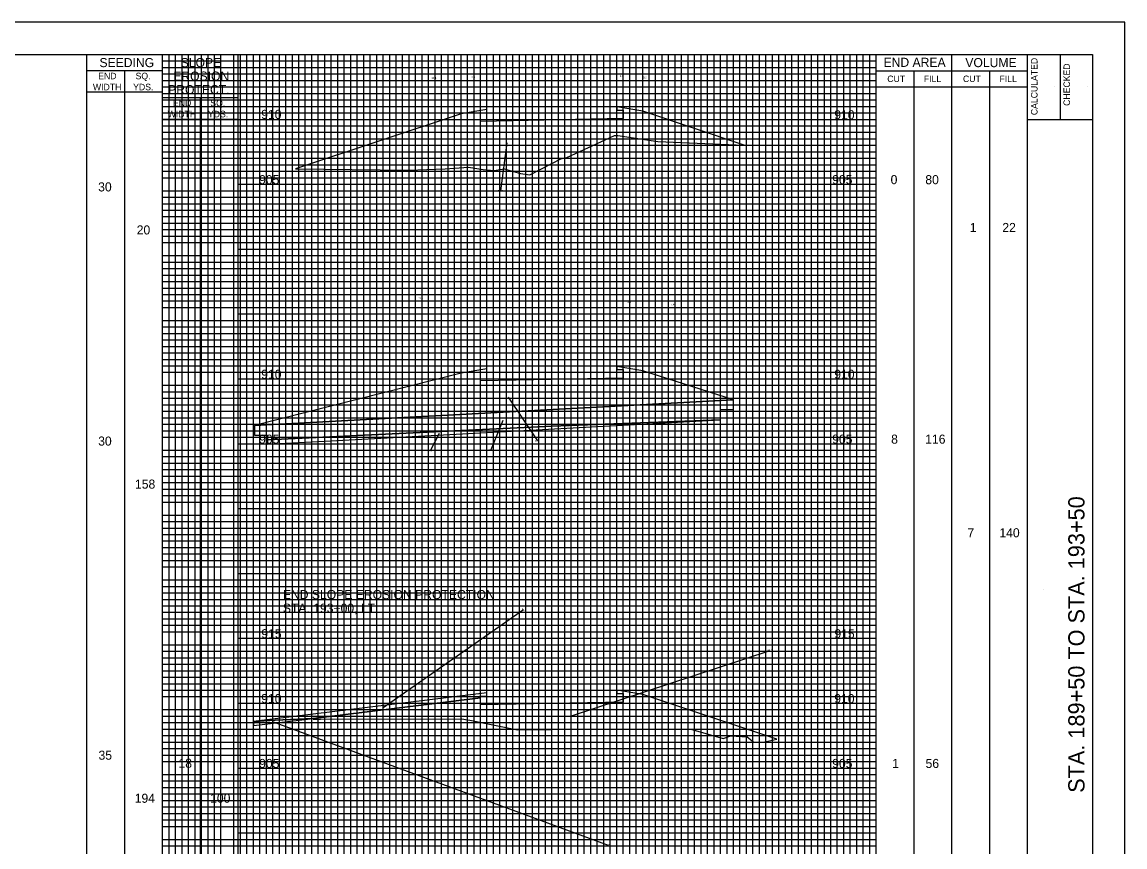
# Model space of a CAD drawing. Extents: x -73 to 160, y -2 to 1877.
# Drawn here: x 75 to 160, y 1078.9 to 1142.5 of the extents above; entities that cross this region are included whole.
import ezdxf

# ---------------------------------------------------------------- set-up
doc = ezdxf.new("R2010")
doc.units = 0
for name, color, linetype in [('DR_P_Flood_Boundary', 7, 'Continuous'), ('GK_Cells', 7, 'Continuous'), ('RD_X_Fence', 7, 'Continuous'), ('TX_X_5', 7, 'Continuous'), ('UT_P_Water_Cells', 7, 'Continuous'), ('XS_P_Pavt_Surface', 7, 'Continuous'), ('XS_X_Ground_Line', 7, 'Continuous')]:
    doc.layers.add(name, color=color, linetype=linetype)

msp = doc.modelspace()

# ---------------------------------------------------------------- linework, layer by layer
at = {"layer": 'DR_P_Flood_Boundary'}
for p, q in [((95.832, 1035), (95.832, 1140)), ((100.832, 1035), (100.832, 1140)), ((105.832, 1035), (105.832, 1140)), ((110.832, 1035), (110.832, 1140)), ((115.832, 1035), (115.832, 1140)), ((120.832, 1035), (120.832, 1140)), ((125.832, 1035), (125.832, 1140)), ((130.832, 1035), (130.832, 1140)), ((135.832, 1035), (135.832, 1140)), ((85.832, 1135), (140.832, 1135)), ((91.665, 1130), (140.832, 1130)), ((91.665, 1125), (140.832, 1125)), ((91.665, 1120), (140.832, 1120)), ((91.665, 1115), (140.832, 1115)), ((91.665, 1110), (140.832, 1110)), ((91.665, 1105), (140.832, 1105)), ((91.665, 1100), (140.832, 1100)), ((91.665, 1095), (140.832, 1095)), ((91.665, 1090), (140.832, 1090)), ((91.665, 1085), (140.832, 1085)), ((91.665, 1080), (140.832, 1080))]:
    msp.add_line(p, q, dxfattribs=at)
at = {"layer": 'GK_Cells'}
for p, q in [((152.5, 1035), (152.5, 1140)), ((155, 1140), (155, 1135)), ((152.5, 1135), (157.5, 1135))]:
    msp.add_line(p, q, dxfattribs=at)
msp.add_lwpolyline([(0, 1140), (157.5, 1140), (157.5, 1035), (0, 1035)], close=True, dxfattribs=at)
at = {"layer": 'RD_X_Fence'}
for p, q in [((110.832, 1135.76), (108.832, 1135.427)), ((122.832, 1135.627), (120.832, 1135.96)), ((120.832, 1135.71), (121.332, 1135.72)), ((121.332, 1135.72), (121.332, 1135.053)), ((130.666, 1133.016), (122.832, 1135.627)), ((108.832, 1135.427), (96.073, 1131.173)), ((110.332, 1135.5), (110.832, 1135.51)), ((110.332, 1134.833), (110.332, 1135.5)), ((121.332, 1135.053), (110.332, 1134.833)), ((112.363, 1133.182), (111.883, 1129.484)), ((108.832, 1115.427), (92.913, 1111.4)), ((110.832, 1115.76), (108.832, 1115.427)), ((110.332, 1115.5), (110.832, 1115.51)), ((110.332, 1114.833), (110.332, 1115.5)), ((122.832, 1115.627), (120.832, 1115.96)), ((120.832, 1115.71), (121.332, 1115.72)), ((121.332, 1115.72), (121.332, 1115.053)), ((129.832, 1113.38), (122.832, 1115.627)), ((121.332, 1115.053), (110.332, 1114.833)), ((112.458, 1113.586), (114.719, 1110.214)), ((129.832, 1113.38), (92.913, 1111.4)), ((92.913, 1111.4), (129.832, 1113.38)), ((129.832, 1112.63), (129.832, 1113.38)), ((115.832, 1111.343), (128.832, 1111.842)), ((128.832, 1112.63), (129.832, 1112.63)), ((128.832, 1111.842), (128.832, 1112.63)), ((128.832, 1111.826), (128.832, 1111.842)), ((92.913, 1111.4), (92.913, 1110.65)), ((93.913, 1110.307), (115.832, 1111.343)), ((112.056, 1111.792), (111.124, 1109.523)), ((92.913, 1110.65), (93.913, 1110.65)), ((93.913, 1110.65), (93.913, 1110.307)), ((93.913, 1110.307), (93.913, 1109.954)), ((107.153, 1110.794), (106.465, 1109.448)), ((102.834, 1089.661), (113.657, 1097.229)), ((117.267, 1088.992), (132.665, 1094.068)), ((110.832, 1090.792), (92.832, 1088.597)), ((122.832, 1090.659), (120.832, 1090.992)), ((120.832, 1090.742), (121.332, 1090.752)), ((121.332, 1090.752), (121.332, 1090.086)), ((133.172, 1087.213), (122.832, 1090.659)), ((110.332, 1090.401), (97.435, 1088.828)), ((97.435, 1088.828), (110.332, 1090.401)), ((110.332, 1090.532), (110.832, 1090.542)), ((110.332, 1090.401), (110.332, 1090.532)), ((110.332, 1089.866), (110.332, 1090.401)), ((121.332, 1090.086), (110.332, 1089.866)), ((92.832, 1088.267), (97.435, 1088.828)), ((94.508, 1088.677), (92.832, 1088.597)), ((92.832, 1088.597), (92.832, 1088.267)), ((94.359, 1088.562), (120.181, 1079.042)), ((97.435, 1088.828), (94.508, 1088.677))]:
    msp.add_line(p, q, dxfattribs=at)
for points in [[(110.832, 1135.51), (110.832, 1135.656), (110.832, 1135.76)], [(120.832, 1135.96), (120.832, 1135.856), (120.832, 1135.71)], [(96.073, 1131.173), (104.784, 1131.084), (107.603, 1131.193), (109.398, 1131.309), (110.538, 1131.143), (111.396, 1131.055), (112.145, 1131.194), (113.421, 1130.814), (114.132, 1130.712), (115.833, 1131.587), (116.533, 1131.948), (116.999, 1132.07), (120.651, 1133.759), (120.929, 1133.75), (123.991, 1133.297), (130.666, 1133.016)], [(110.832, 1115.51), (110.832, 1115.656), (110.832, 1115.76)], [(120.832, 1115.96), (120.832, 1115.856), (120.832, 1115.71)], [(128.832, 1111.842), (115.832, 1111.343), (93.913, 1110.307)], [(93.913, 1109.954), (108.948, 1110.76), (128.832, 1111.826)], [(110.832, 1090.542), (110.832, 1090.688), (110.832, 1090.792)], [(120.832, 1090.992), (120.832, 1090.888), (120.832, 1090.742)], [(92.832, 1088.597), (94.508, 1088.677), (97.435, 1088.828)], [(97.435, 1088.828), (97.444, 1088.756)], [(97.444, 1088.756), (97.991, 1088.773), (108.881, 1088.802), (109.332, 1088.712)], [(109.332, 1088.712), (109.332, 1088.712)], [(109.332, 1088.712), (109.512, 1088.676), (113.184, 1087.945), (115.832, 1087.956)], [(115.832, 1087.956), (122.332, 1087.984), (126.55, 1088.003), (129.023, 1087.274), (129.616, 1087.479), (130.873, 1087.395), (131.395, 1086.992), (132.249, 1087.017), (133.172, 1087.213)]]:
    msp.add_lwpolyline(points, dxfattribs=at)
at = {"layer": 'TX_X_5'}
msp.add_lwpolyline([(-10, 1032.5), (160, 1032.5), (160, 1142.5), (-10, 1142.5)], close=True, dxfattribs=at)
at = {"layer": 'UT_P_Water_Cells'}
for p, q in [((86.332, 1035), (86.332, 1140)), ((86.832, 1035), (86.832, 1140)), ((87.332, 1035), (87.332, 1140)), ((87.832, 1035), (87.832, 1140)), ((88.332, 1035), (88.332, 1140)), ((88.832, 1035), (88.832, 1140)), ((89.332, 1035), (89.332, 1140)), ((89.832, 1035), (89.832, 1140)), ((90.332, 1035), (90.332, 1140)), ((91.332, 1035), (91.332, 1140)), ((91.832, 1035), (91.832, 1140)), ((92.332, 1035), (92.332, 1140)), ((92.832, 1035), (92.832, 1140)), ((93.332, 1035), (93.332, 1140)), ((93.832, 1035), (93.832, 1140)), ((94.332, 1035), (94.332, 1140)), ((94.832, 1035), (94.832, 1140)), ((95.332, 1035), (95.332, 1140)), ((96.332, 1035), (96.332, 1140)), ((96.832, 1035), (96.832, 1140)), ((97.332, 1035), (97.332, 1140)), ((97.832, 1035), (97.832, 1140)), ((98.332, 1035), (98.332, 1140)), ((98.832, 1035), (98.832, 1140)), ((99.332, 1035), (99.332, 1140)), ((99.832, 1035), (99.832, 1140)), ((100.332, 1035), (100.332, 1140)), ((101.332, 1035), (101.332, 1140)), ((101.832, 1035), (101.832, 1140)), ((102.332, 1035), (102.332, 1140)), ((102.832, 1035), (102.832, 1140)), ((103.332, 1035), (103.332, 1140)), ((103.832, 1035), (103.832, 1140)), ((104.332, 1035), (104.332, 1140)), ((104.832, 1035), (104.832, 1140)), ((105.332, 1035), (105.332, 1140)), ((106.332, 1035), (106.332, 1140)), ((106.832, 1035), (106.832, 1140)), ((107.332, 1035), (107.332, 1140)), ((107.832, 1035), (107.832, 1140)), ((108.332, 1035), (108.332, 1140)), ((108.832, 1035), (108.832, 1140)), ((109.332, 1035), (109.332, 1140)), ((109.832, 1035), (109.832, 1140)), ((110.332, 1035), (110.332, 1140)), ((111.332, 1035), (111.332, 1140)), ((111.832, 1035), (111.832, 1140)), ((112.332, 1035), (112.332, 1140)), ((112.832, 1035), (112.832, 1140)), ((113.332, 1035), (113.332, 1140)), ((113.832, 1035), (113.832, 1140)), ((114.332, 1035), (114.332, 1140)), ((114.832, 1035), (114.832, 1140)), ((115.332, 1035), (115.332, 1140)), ((116.332, 1035), (116.332, 1140)), ((116.832, 1035), (116.832, 1140)), ((117.332, 1035), (117.332, 1140)), ((117.832, 1035), (117.832, 1140)), ((118.332, 1035), (118.332, 1140)), ((118.832, 1035), (118.832, 1140)), ((119.332, 1035), (119.332, 1140)), ((119.832, 1035), (119.832, 1140)), ((120.332, 1035), (120.332, 1140)), ((121.332, 1035), (121.332, 1140)), ((121.832, 1035), (121.832, 1140)), ((122.332, 1035), (122.332, 1140)), ((122.832, 1035), (122.832, 1140)), ((123.332, 1035), (123.332, 1140)), ((123.832, 1035), (123.832, 1140)), ((124.332, 1035), (124.332, 1140)), ((124.832, 1035), (124.832, 1140)), ((125.332, 1035), (125.332, 1140)), ((126.332, 1035), (126.332, 1140)), ((126.832, 1035), (126.832, 1140)), ((127.332, 1035), (127.332, 1140)), ((127.832, 1035), (127.832, 1140)), ((128.332, 1035), (128.332, 1140)), ((128.832, 1035), (128.832, 1140)), ((129.332, 1035), (129.332, 1140)), ((129.832, 1035), (129.832, 1140)), ((130.332, 1035), (130.332, 1140)), ((131.332, 1035), (131.332, 1140)), ((131.832, 1035), (131.832, 1140)), ((132.332, 1035), (132.332, 1140)), ((132.832, 1035), (132.832, 1140)), ((133.332, 1035), (133.332, 1140)), ((133.832, 1035), (133.832, 1140)), ((134.332, 1035), (134.332, 1140)), ((134.832, 1035), (134.832, 1140)), ((135.332, 1035), (135.332, 1140)), ((136.332, 1035), (136.332, 1140)), ((136.832, 1035), (136.832, 1140)), ((137.332, 1035), (137.332, 1140)), ((137.832, 1035), (137.832, 1140)), ((138.332, 1035), (138.332, 1140)), ((138.832, 1035), (138.832, 1140)), ((139.332, 1035), (139.332, 1140)), ((139.832, 1035), (139.832, 1140)), ((140.332, 1035), (140.332, 1140)), ((85.832, 1139.5), (140.832, 1139.5)), ((85.832, 1139), (140.832, 1139)), ((85.832, 1138.5), (140.832, 1138.5)), ((85.832, 1138), (140.832, 1138)), ((85.832, 1137.5), (140.832, 1137.5)), ((85.832, 1137), (140.832, 1137)), ((85.832, 1136.5), (140.832, 1136.5)), ((85.832, 1136), (140.832, 1136)), ((85.832, 1135.5), (140.832, 1135.5)), ((85.832, 1134.5), (140.832, 1134.5)), ((85.832, 1134), (140.832, 1134)), ((85.832, 1133.5), (140.832, 1133.5)), ((85.832, 1133), (140.832, 1133)), ((85.832, 1132.5), (140.832, 1132.5)), ((85.832, 1132), (140.832, 1132)), ((85.832, 1131.5), (140.832, 1131.5)), ((85.832, 1131), (140.832, 1131)), ((85.832, 1130.5), (140.832, 1130.5)), ((85.832, 1129.5), (140.832, 1129.5)), ((85.832, 1129), (140.832, 1129)), ((85.832, 1128.5), (140.832, 1128.5)), ((85.832, 1128), (140.832, 1128)), ((85.832, 1127.5), (140.832, 1127.5)), ((85.832, 1127), (140.832, 1127)), ((85.832, 1126.5), (140.832, 1126.5)), ((85.832, 1126), (140.832, 1126)), ((85.832, 1125.5), (140.832, 1125.5)), ((85.832, 1124.5), (140.832, 1124.5)), ((85.832, 1124), (140.832, 1124)), ((85.832, 1123.5), (140.832, 1123.5)), ((85.832, 1123), (140.832, 1123)), ((85.832, 1122.5), (140.832, 1122.5)), ((85.832, 1122), (140.832, 1122)), ((85.832, 1121.5), (140.832, 1121.5)), ((85.832, 1121), (140.832, 1121)), ((85.832, 1120.5), (140.832, 1120.5)), ((85.832, 1119.5), (140.832, 1119.5)), ((85.832, 1119), (140.832, 1119)), ((85.832, 1118.5), (140.832, 1118.5)), ((85.832, 1118), (140.832, 1118)), ((85.832, 1117.5), (140.832, 1117.5)), ((85.832, 1117), (140.832, 1117)), ((85.832, 1116.5), (140.832, 1116.5)), ((85.832, 1116), (140.832, 1116)), ((85.832, 1115.5), (140.832, 1115.5)), ((85.832, 1114.5), (140.832, 1114.5)), ((85.832, 1114), (140.832, 1114)), ((85.832, 1113.5), (140.832, 1113.5)), ((85.832, 1113), (140.832, 1113)), ((85.832, 1112.5), (140.832, 1112.5)), ((85.832, 1112), (140.832, 1112)), ((85.832, 1111.5), (140.832, 1111.5)), ((85.832, 1111), (140.832, 1111)), ((85.832, 1110.5), (140.832, 1110.5)), ((85.832, 1109.5), (140.832, 1109.5)), ((85.832, 1109), (140.832, 1109)), ((85.832, 1108.5), (140.832, 1108.5)), ((85.832, 1108), (140.832, 1108)), ((85.832, 1107.5), (140.832, 1107.5)), ((85.832, 1107), (140.832, 1107)), ((85.832, 1106.5), (140.832, 1106.5)), ((85.832, 1106), (140.832, 1106)), ((85.832, 1105.5), (140.832, 1105.5)), ((85.832, 1104.5), (140.832, 1104.5)), ((85.832, 1104), (140.832, 1104)), ((85.832, 1103.5), (140.832, 1103.5)), ((85.832, 1103), (140.832, 1103)), ((85.832, 1102.5), (140.832, 1102.5)), ((85.832, 1102), (140.832, 1102)), ((85.832, 1101.5), (140.832, 1101.5)), ((85.832, 1101), (140.832, 1101)), ((85.832, 1100.5), (140.832, 1100.5)), ((85.832, 1099.5), (140.832, 1099.5)), ((85.832, 1099), (140.832, 1099)), ((85.832, 1098.5), (140.832, 1098.5)), ((85.832, 1098), (140.832, 1098)), ((85.832, 1097.5), (140.832, 1097.5)), ((85.832, 1097), (140.832, 1097)), ((85.832, 1096.5), (140.832, 1096.5)), ((85.832, 1096), (140.832, 1096)), ((85.832, 1095.5), (140.832, 1095.5)), ((85.832, 1094.5), (140.832, 1094.5)), ((85.832, 1094), (140.832, 1094)), ((85.832, 1093.5), (140.832, 1093.5)), ((85.832, 1093), (140.832, 1093)), ((85.832, 1092.5), (140.832, 1092.5)), ((85.832, 1092), (140.832, 1092)), ((85.832, 1091.5), (140.832, 1091.5)), ((85.832, 1091), (140.832, 1091)), ((85.832, 1090.5), (140.832, 1090.5)), ((85.832, 1089.5), (140.832, 1089.5)), ((85.832, 1089), (140.832, 1089)), ((85.832, 1088.5), (140.832, 1088.5)), ((85.832, 1088), (140.832, 1088)), ((85.832, 1087.5), (140.832, 1087.5)), ((85.832, 1087), (140.832, 1087)), ((85.832, 1086.5), (140.832, 1086.5)), ((85.832, 1086), (140.832, 1086)), ((85.832, 1085.5), (140.832, 1085.5)), ((85.832, 1084.5), (140.832, 1084.5)), ((85.832, 1084), (140.832, 1084)), ((85.832, 1083.5), (140.832, 1083.5)), ((85.832, 1083), (140.832, 1083)), ((85.832, 1082.5), (140.832, 1082.5)), ((85.832, 1082), (140.832, 1082)), ((85.832, 1081.5), (140.832, 1081.5)), ((85.832, 1081), (140.832, 1081)), ((85.832, 1080.5), (140.832, 1080.5)), ((85.832, 1079.5), (140.832, 1079.5)), ((85.832, 1079), (140.832, 1079))]:
    msp.add_line(p, q, dxfattribs=at)
at = {"layer": 'XS_X_Ground_Line'}
for p, q in [((80, 1035), (80, 1140)), ((85.832, 1035), (85.832, 1140)), ((85.832, 1035), (85.832, 1140)), ((91.665, 1035), (91.665, 1140)), ((140.832, 1035), (140.832, 1140)), ((146.667, 1035), (146.667, 1140)), ((85.832, 1138.75), (80, 1138.75)), ((82.916, 1035), (82.916, 1138.75)), ((140.832, 1138.75), (152.5, 1138.75)), ((143.75, 1035), (143.75, 1138.75)), ((149.583, 1035), (149.583, 1138.75)), ((140.832, 1137.5), (152.5, 1137.5)), ((154.6, 1137.518), (154.6, 1137.518)), ((157.1, 1137.518), (157.1, 1137.518)), ((85.832, 1137.083), (80, 1137.083)), ((91.665, 1136.667), (85.832, 1136.667)), ((88.749, 1035), (88.749, 1136.667)), ((91.665, 1135), (85.832, 1135)), ((153.75, 1098.75), (153.75, 1098.75)), ((156.258, 1098.75), (156.258, 1098.75))]:
    msp.add_line(p, q, dxfattribs=at)

# ---------------------------------------------------------------- texts
at = {"layer": 'RD_X_Fence'}
for s, p in [('13.4', (106.55, 1138.113)), ('2.0', (109.642, 1138.176)), ('2.0', (121.062, 1138.271)), ('8.3', (122.865, 1138.145)), ('79.5', (111.676, 1129.414)), ('16.4', (105.535, 1121.173)), ('2.0', (121.67, 1120.856)), ('7.4', (125.002, 1120.658)), ('69.2', (114.511, 1110.144)), ('7.7', (106.32, 1109.378)), ('46.2', (110.916, 1109.453)), ('5.1', (113.522, 1097.159)), ('50.3', (132.438, 1093.998)), ('0.7', (120.012, 1078.972))]:
    msp.add_text(s, height=0.14, dxfattribs=at).set_placement(p)
at = {"layer": 'XS_P_Pavt_Surface'}
for s, p in [('910', (93.43, 1135.031)), ('910', (137.598, 1135)), ('905', (93.27, 1130)), ('905', (137.438, 1130)), ('0', (141.941, 1130)), ('80', (144.615, 1130)), ('30', (80.866, 1129.444)), ('20', (83.836, 1126.128)), ('1', (148.04, 1126.314)), ('22', (150.551, 1126.314)), ('910', (93.43, 1115)), ('910', (137.598, 1115)), ('30', (80.866, 1109.851)), ('905', (93.27, 1110)), ('905', (137.438, 1110)), ('8', (141.98, 1110)), ('116', (144.607, 1110)), ('158', (83.704, 1106.534)), ('7', (147.861, 1102.783)), ('140', (150.325, 1102.783)), ('END SLOPE EROSION PROTECTION', (95.101, 1098.02)), ('STA. 193+00, LT.', (95.101, 1096.97)), ('915', (93.441, 1095)), ('915', (137.609, 1095)), ('910', (93.43, 1090)), ('910', (137.598, 1090)), ('35', (80.893, 1085.637)), ('18', (87.054, 1085.017)), ('905', (93.27, 1085)), ('905', (137.438, 1085)), ('1', (142.057, 1085)), ('56', (144.634, 1085)), ('194', (83.682, 1082.32)), ('100', (89.496, 1082.32))]:
    msp.add_text(s, height=0.7, dxfattribs=at).set_placement(p)
at = {"layer": 'XS_X_Ground_Line'}
for s, height, p in [('SEEDING', 0.7, (80.964, 1139.025)), ('SLOPE', 0.7, (87.228, 1139.025)), ('END AREA', 0.7, (141.394, 1139.047)), ('VOLUME', 0.7, (147.698, 1139.025)), ('END', 0.5, (80.87, 1138.092)), ('SQ.', 0.5, (83.748, 1138.092)), ('EROSION', 0.7, (86.649, 1137.983)), ('CUT', 0.5, (141.683, 1137.875)), ('FILL', 0.5, (144.502, 1137.875)), ('CUT', 0.5, (147.517, 1137.875)), ('FILL', 0.5, (150.335, 1137.875)), ('WIDTH', 0.5, (80.462, 1137.242)), ('YDS.', 0.5, (83.563, 1137.242)), ('PROTECT.', 0.7, (86.26, 1136.942)), ('END', 0.5, (86.631, 1136.008)), ('SQ.', 0.5, (89.51, 1136.008)), ('WIDTH', 0.5, (86.224, 1135.158)), ('YDS.', 0.5, (89.325, 1135.158))]:
    msp.add_text(s, height=height, dxfattribs=at).set_placement(p)
for s, height, p in [('CALCULATED', 0.5, (153.262, 1135.323)), ('CHECKED', 0.5, (155.762, 1136.04)), ('STA. 189+50 TO STA. 193+50', 1.25, (156.883, 1083.086))]:
    msp.add_text(s, height=height, rotation=90, dxfattribs=at).set_placement(p)

doc.saveas('drawing.dxf')
